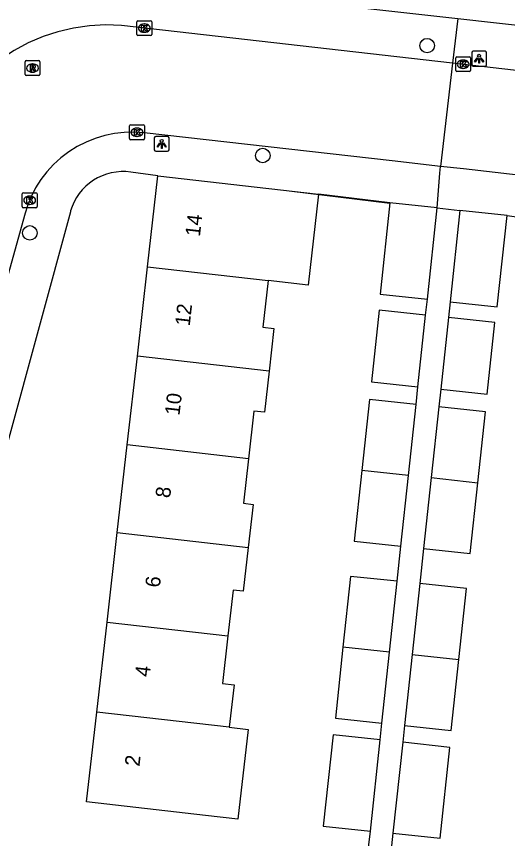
# Model space of a CAD drawing. Extents: x 162026 to 163499, y 387297 to 388169.
# Drawn here: x 162383.6 to 162416.7, y 387852 to 387907.4 of the extents above; entities that cross this region are included whole.
import ezdxf

# ---------------------------------------------------------------- set-up
doc = ezdxf.new("R2010")
doc.units = 0
for name, color, linetype in [('IMGEO_Boom', 7, 'Continuous'), ('IMGEO_Kolk', 7, 'Continuous'), ('IMGEO_Lichtpunt', 7, 'Continuous'), ('IMGEO_Muur', 7, 'Continuous'), ('IMGEO_Pand', 7, 'Continuous'), ('IMGEO_Pand_nummerreeks', 7, 'Continuous'), ('IMGEO_Rijbaan_lokaal_open', 7, 'Continuous'), ('IMGEO_Rioolput', 7, 'Continuous'), ('IMGEO_Voetpad_open', 7, 'Continuous')]:
    doc.layers.add(name, color=color, linetype=linetype)

msp = doc.modelspace()

# ---------------------------------------------------------------- linework, layer by layer
at = {"layer": 'IMGEO_Boom'}
for centre in [(162411.289, 387905.434), (162400.199, 387898.028), (162384.482, 387892.813)]:
    msp.add_circle(centre, 0.489, dxfattribs=at)
at = {"layer": 'IMGEO_Kolk'}
for p, q in [((162391.705, 387906.189), (162391.705, 387907.041)), ((162391.78, 387907.115), (162392.632, 387907.115)), ((162392.193, 387906.895), (162392.218, 387906.895)), ((162392.706, 387907.041), (162392.706, 387906.189)), ((162392.632, 387906.115), (162391.78, 387906.115)), ((162392.216, 387906.335), (162392.191, 387906.335)), ((162413.218, 387903.755), (162413.218, 387904.607)), ((162413.293, 387904.681), (162414.145, 387904.681)), ((162413.706, 387904.461), (162413.731, 387904.461)), ((162414.219, 387904.607), (162414.219, 387903.755)), ((162413.729, 387903.901), (162413.704, 387903.901)), ((162414.145, 387903.681), (162413.293, 387903.681)), ((162391.212, 387899.166), (162391.212, 387900.018)), ((162391.287, 387900.092), (162392.139, 387900.092)), ((162392.213, 387900.018), (162392.213, 387899.166)), ((162391.7, 387899.872), (162391.725, 387899.872)), ((162392.139, 387899.092), (162391.287, 387899.092)), ((162391.723, 387899.312), (162391.698, 387899.312)), ((162383.969, 387894.584), (162383.969, 387895.436)), ((162384.044, 387895.51), (162384.896, 387895.51)), ((162384.457, 387895.29), (162384.482, 387895.29)), ((162384.97, 387895.436), (162384.97, 387894.584)), ((162384.896, 387894.51), (162384.044, 387894.51)), ((162384.48, 387894.73), (162384.455, 387894.73))]:
    msp.add_line(p, q, dxfattribs=at)
for points in [[(162391.705, 387906.189), (162391.705, 387907.041)], [(162391.78, 387907.115), (162392.632, 387907.115)], [(162392.026, 387906.815), (162392.149, 387906.815), (162392.149, 387906.664), (162392.279, 387906.815), (162392.443, 387906.815), (162392.297, 387906.664), (162392.45, 387906.415), (162392.298, 387906.415), (162392.213, 387906.579), (162392.149, 387906.512), (162392.149, 387906.415), (162392.026, 387906.415), (162392.026, 387906.815)], [(162392.706, 387907.041), (162392.706, 387906.189)], [(162392.632, 387906.115), (162391.78, 387906.115)], [(162413.218, 387903.755), (162413.218, 387904.607)], [(162413.293, 387904.681), (162414.145, 387904.681)], [(162414.219, 387904.607), (162414.219, 387903.755)], [(162413.539, 387904.381), (162413.662, 387904.381), (162413.662, 387904.23), (162413.792, 387904.381), (162413.956, 387904.381), (162413.81, 387904.23), (162413.963, 387903.981), (162413.811, 387903.981), (162413.726, 387904.145), (162413.662, 387904.078), (162413.662, 387903.981), (162413.539, 387903.981), (162413.539, 387904.381)], [(162414.145, 387903.681), (162413.293, 387903.681)], [(162391.212, 387899.166), (162391.212, 387900.018)], [(162391.287, 387900.092), (162392.139, 387900.092)], [(162392.213, 387900.018), (162392.213, 387899.166)], [(162391.533, 387899.792), (162391.656, 387899.792), (162391.656, 387899.641), (162391.786, 387899.792), (162391.95, 387899.792), (162391.804, 387899.641), (162391.957, 387899.392), (162391.805, 387899.392), (162391.72, 387899.556), (162391.656, 387899.489), (162391.656, 387899.392), (162391.533, 387899.392), (162391.533, 387899.792)], [(162392.139, 387899.092), (162391.287, 387899.092)], [(162383.969, 387894.584), (162383.969, 387895.436)], [(162384.044, 387895.51), (162384.896, 387895.51)], [(162384.29, 387895.21), (162384.413, 387895.21), (162384.413, 387895.059), (162384.543, 387895.21), (162384.707, 387895.21), (162384.561, 387895.059), (162384.714, 387894.81), (162384.562, 387894.81), (162384.477, 387894.974), (162384.413, 387894.907), (162384.413, 387894.81), (162384.29, 387894.81), (162384.29, 387895.21)], [(162384.97, 387895.436), (162384.97, 387894.584)], [(162384.896, 387894.51), (162384.044, 387894.51)]]:
    msp.add_lwpolyline(points, dxfattribs=at)
for centre, start, end in [((162391.782, 387907.039), 91.552, 178.448), ((162391.782, 387907.039), 91.552, 178.448), ((162392.63, 387907.039), 1.552, 88.448), ((162392.63, 387907.039), 1.552, 88.448), ((162391.782, 387906.191), 181.552, 268.448), ((162391.782, 387906.191), 181.552, 268.448), ((162392.63, 387906.191), 271.552, 358.448), ((162392.63, 387906.191), 271.552, 358.448), ((162413.295, 387904.605), 91.552, 178.448), ((162413.295, 387904.605), 91.552, 178.448), ((162414.143, 387904.605), 1.552, 88.448), ((162414.143, 387904.605), 1.552, 88.448), ((162413.295, 387903.757), 181.552, 268.448), ((162413.295, 387903.757), 181.552, 268.448), ((162414.143, 387903.757), 271.552, 358.448), ((162414.143, 387903.757), 271.552, 358.448), ((162391.289, 387900.016), 91.552, 178.448), ((162391.289, 387900.016), 91.552, 178.448), ((162392.137, 387900.016), 1.552, 88.448), ((162392.137, 387900.016), 1.552, 88.448), ((162391.289, 387899.168), 181.552, 268.448), ((162391.289, 387899.168), 181.552, 268.448), ((162392.137, 387899.168), 271.552, 358.448), ((162392.137, 387899.168), 271.552, 358.448), ((162384.046, 387895.434), 91.552, 178.448), ((162384.046, 387895.434), 91.552, 178.448), ((162384.894, 387895.434), 1.552, 88.448), ((162384.894, 387895.434), 1.552, 88.448), ((162384.046, 387894.586), 181.552, 268.448), ((162384.046, 387894.586), 181.552, 268.448), ((162384.894, 387894.586), 271.552, 358.448), ((162384.894, 387894.586), 271.552, 358.448)]:
    msp.add_arc(centre, 0.0765, start, end, dxfattribs=at)
for centre, major_axis, ratio, start_param, end_param in [((162392.192, 387906.615), (-0.387, 0.002), 0.722429, 4.712389, 7.853982), ((162392.217, 387906.615), (-0.39, 0.002), 0.717154, 1.570796, 4.712389), ((162413.705, 387904.181), (-0.387, 0.002), 0.722429, 4.712389, 7.853982), ((162413.73, 387904.181), (-0.39, 0.002), 0.717154, 1.570796, 4.712389), ((162391.699, 387899.592), (-0.387, 0.002), 0.722429, 4.712389, 7.853982), ((162391.724, 387899.592), (-0.39, 0.002), 0.717154, 1.570796, 4.712389), ((162384.456, 387895.01), (-0.387, 0.002), 0.722429, 4.712389, 7.853982), ((162384.481, 387895.01), (-0.39, 0.002), 0.717154, 1.570796, 4.712389)]:
    msp.add_ellipse(centre, major_axis=major_axis, ratio=ratio, start_param=start_param, end_param=end_param, dxfattribs=at)
at = {"layer": 'IMGEO_Lichtpunt'}
for p, q in [((162414.299, 387904.956), (162414.299, 387904.149)), ((162414.299, 387904.956), (162414.299, 387904.149)), ((162415.201, 387905.051), (162414.393, 387905.051)), ((162415.201, 387905.051), (162414.393, 387905.051)), ((162415.295, 387904.149), (162415.295, 387904.956)), ((162415.295, 387904.149), (162415.295, 387904.956)), ((162414.393, 387904.055), (162415.201, 387904.055)), ((162414.393, 387904.055), (162415.201, 387904.055)), ((162392.879, 387899.214), (162392.879, 387898.407)), ((162392.879, 387899.214), (162392.879, 387898.407)), ((162393.781, 387899.309), (162392.973, 387899.309)), ((162393.781, 387899.309), (162392.973, 387899.309)), ((162393.875, 387898.407), (162393.875, 387899.214)), ((162393.875, 387898.407), (162393.875, 387899.214)), ((162392.973, 387898.313), (162393.781, 387898.313)), ((162392.973, 387898.313), (162393.781, 387898.313))]:
    msp.add_line(p, q, dxfattribs=at)
for points in [[(162414.673, 387904.62), (162414.712, 387904.592), (162414.524, 387904.33), (162414.486, 387904.357), (162414.673, 387904.62)], [(162414.775, 387904.572), (162414.822, 387904.572), (162414.822, 387904.25), (162414.775, 387904.25), (162414.775, 387904.572)], [(162414.885, 387904.592), (162414.923, 387904.619), (162415.11, 387904.357), (162415.071, 387904.329), (162414.885, 387904.592)], [(162393.253, 387898.878), (162393.292, 387898.85), (162393.104, 387898.588), (162393.066, 387898.615), (162393.253, 387898.878)], [(162393.465, 387898.85), (162393.503, 387898.877), (162393.69, 387898.615), (162393.651, 387898.587), (162393.465, 387898.85)], [(162393.355, 387898.83), (162393.402, 387898.83), (162393.402, 387898.508), (162393.355, 387898.508), (162393.355, 387898.83)]]:
    msp.add_lwpolyline(points, dxfattribs=at)
for centre in [(162414.798, 387904.754), (162393.378, 387899.012)]:
    msp.add_circle(centre, 0.0994, dxfattribs=at)
for centre, start, end in [((162414.393, 387904.956), 90, 180), ((162414.393, 387904.956), 90, 180), ((162415.201, 387904.956), 0, 90), ((162415.201, 387904.956), 0, 90), ((162414.393, 387904.149), 180, 270), ((162414.393, 387904.149), 180, 270), ((162415.201, 387904.149), 270, 0), ((162415.201, 387904.149), 270, 360), ((162392.973, 387899.214), 90, 180), ((162392.973, 387899.214), 90, 180), ((162393.781, 387899.214), 0, 90), ((162393.781, 387899.214), 0, 90), ((162392.973, 387898.407), 180, 270), ((162392.973, 387898.407), 180, 270), ((162393.781, 387898.407), 270, 0), ((162393.781, 387898.407), 270, 360)]:
    msp.add_arc(centre, 0.0946, start, end, dxfattribs=at)
at = {"layer": 'IMGEO_Muur'}
msp.add_lwpolyline([(162402.165, 387895.619), (162408.764, 387894.82)], dxfattribs=at)
at = {"layer": 'IMGEO_Pand'}
for points in [[(162392.425, 387890.522), (162393.125, 387896.651)], [(162393.125, 387896.651), (162403.967, 387895.413)], [(162403.967, 387895.413), (162403.267, 387889.284), (162400.563, 387889.593)], [(162408.78, 387894.837), (162408.121, 387888.692), (162411.303, 387888.351)], [(162411.961, 387894.496), (162408.78, 387894.837)], [(162411.303, 387888.351), (162411.961, 387894.496)], [(162413.502, 387894.329), (162412.838, 387888.168)], [(162412.838, 387888.168), (162416.02, 387887.825), (162416.683, 387893.987)], [(162416.683, 387893.987), (162413.502, 387894.329)], [(162391.737, 387884.5), (162392.425, 387890.522)], [(162392.425, 387890.522), (162400.563, 387889.593)], [(162400.563, 387889.593), (162400.205, 387886.46), (162400.955, 387886.374), (162400.625, 387883.485)], [(162411.186, 387887.258), (162408.044, 387887.595), (162407.528, 387882.781), (162410.67, 387882.444)], [(162410.67, 387882.444), (162411.186, 387887.258)], [(162412.724, 387887.101), (162412.204, 387882.273)], [(162412.204, 387882.273), (162415.346, 387881.935), (162415.865, 387886.763), (162412.724, 387887.101)], [(162391.054, 387878.526), (162391.737, 387884.5)], [(162400.625, 387883.485), (162391.737, 387884.5)], [(162400.625, 387883.485), (162400.309, 387880.719), (162399.6, 387880.8), (162399.234, 387877.592)], [(162410.541, 387881.241), (162407.399, 387881.578), (162406.888, 387876.805)], [(162410.03, 387876.468), (162410.541, 387881.241)], [(162412.077, 387881.095), (162411.562, 387876.312)], [(162414.704, 387875.974), (162415.219, 387880.756), (162412.077, 387881.095)], [(162390.378, 387872.606), (162391.054, 387878.526)], [(162399.234, 387877.592), (162391.054, 387878.526)], [(162399.234, 387877.592), (162398.89, 387874.586), (162399.553, 387874.51), (162399.22, 387871.596)], [(162406.888, 387876.805), (162406.377, 387872.033), (162409.519, 387871.697)], [(162410.03, 387876.468), (162406.888, 387876.805)], [(162409.519, 387871.697), (162410.03, 387876.468)], [(162411.562, 387876.312), (162411.047, 387871.534)], [(162411.562, 387876.312), (162414.704, 387875.974)], [(162411.047, 387871.534), (162414.189, 387871.196), (162414.704, 387875.974)], [(162389.69, 387866.582), (162390.378, 387872.606)], [(162390.378, 387872.606), (162399.22, 387871.596)], [(162399.22, 387871.596), (162398.883, 387868.651), (162398.195, 387868.729), (162397.843, 387865.651)], [(162409.265, 387869.324), (162406.123, 387869.66), (162405.611, 387864.888)], [(162408.753, 387864.551), (162409.265, 387869.324)], [(162410.793, 387869.173), (162410.278, 387864.391)], [(162413.42, 387864.052), (162413.935, 387868.835), (162410.793, 387869.173)], [(162388.996, 387860.507), (162389.69, 387866.582)], [(162389.69, 387866.582), (162397.843, 387865.651)], [(162397.843, 387865.651), (162397.477, 387862.443), (162398.259, 387862.354), (162398.196, 387861.796), (162397.934, 387859.486)], [(162405.611, 387864.888), (162405.099, 387860.109), (162408.241, 387859.772)], [(162408.753, 387864.551), (162405.611, 387864.888)], [(162408.241, 387859.772), (162408.753, 387864.551)], [(162410.278, 387864.391), (162409.762, 387859.598)], [(162409.762, 387859.598), (162412.904, 387859.259), (162413.42, 387864.052)], [(162410.278, 387864.391), (162413.42, 387864.052)], [(162397.934, 387859.486), (162399.222, 387859.326), (162398.519, 387853.292), (162396.339, 387853.531), (162388.304, 387854.449), (162388.996, 387860.507)], [(162397.934, 387859.486), (162388.996, 387860.507)], [(162408.12, 387858.642), (162404.938, 387858.982), (162404.278, 387852.819), (162407.46, 387852.478)], [(162407.46, 387852.478), (162408.12, 387858.642)], [(162409.641, 387858.474), (162408.981, 387852.343)], [(162408.981, 387852.343), (162412.162, 387852), (162412.823, 387858.131), (162409.641, 387858.474)]]:
    msp.add_lwpolyline(points, dxfattribs=at)
at = {"layer": 'IMGEO_Rijbaan_lokaal_open'}
for points in [[(162413.007, 387904.243), (162390.676, 387906.786), (162389.589, 387906.828), (162388.503, 387906.772), (162387.427, 387906.62), (162386.368, 387906.372), (162385.377, 387906.046), (162384.377, 387905.617), (162383.42, 387905.1), (162382.513, 387904.5), (162381.663, 387903.821), (162380.877, 387903.069), (162380.456, 387902.605), (162380.22, 387902.293), (162379.442, 387901.135), (162378.771, 387899.911), (162378.211, 387898.633), (162377.769, 387897.31), (162377.721, 387897.14), (162366.207, 387855.262)], [(162413.007, 387904.243), (162412.195, 387897.296)], [(162444.639, 387872.789), (162446.538, 387889.5), (162446.633, 387890.462), (162446.642, 387891.428), (162446.564, 387892.391), (162446.401, 387893.343), (162446.153, 387894.277), (162445.823, 387895.185), (162445.413, 387896.06), (162444.926, 387896.895), (162444.367, 387897.683), (162443.739, 387898.417), (162443.049, 387899.093), (162442.967, 387899.166), (162442.491, 387899.581), (162441.98, 387899.952), (162441.438, 387900.276), (162440.869, 387900.549), (162440.608, 387900.655), (162439.709, 387900.991), (162438.784, 387901.246), (162437.9, 387901.409), (162413.007, 387904.243)], [(162412.195, 387897.296), (162408.934, 387897.664), (162392.187, 387899.556), (162391.521, 387899.6), (162390.853, 387899.585), (162390.19, 387899.51), (162389.535, 387899.376), (162388.896, 387899.184), (162388.276, 387898.936), (162387.681, 387898.633), (162387.115, 387898.278), (162386.583, 387897.875), (162386.089, 387897.425), (162385.638, 387896.933), (162385.232, 387896.403), (162384.875, 387895.838), (162384.57, 387895.244), (162384.319, 387894.625), (162384.168, 387894.147), (162373.517, 387855.908)], [(162435.074, 387848.602), (162439.395, 387888.569), (162439.426, 387889.074), (162439.412, 387889.579), (162439.353, 387890.081), (162439.249, 387890.576), (162439.101, 387891.06), (162438.911, 387891.528), (162438.68, 387891.978), (162438.409, 387892.405), (162438.102, 387892.806), (162437.759, 387893.178), (162437.385, 387893.518), (162436.982, 387893.824), (162436.554, 387894.092), (162436.103, 387894.32), (162435.633, 387894.508), (162435.149, 387894.653), (162434.653, 387894.754), (162434.418, 387894.786), (162417.443, 387896.703), (162413.741, 387897.121), (162412.195, 387897.296)]]:
    msp.add_lwpolyline(points, dxfattribs=at)
at = {"layer": 'IMGEO_Rioolput'}
for p, q in [((162384.237, 387904.425), (162385.089, 387904.425)), ((162384.162, 387903.499), (162384.162, 387904.351)), ((162384.65, 387904.205), (162384.675, 387904.205)), ((162385.163, 387904.351), (162385.163, 387903.499)), ((162385.089, 387903.425), (162384.237, 387903.425)), ((162384.673, 387903.645), (162384.648, 387903.645))]:
    msp.add_line(p, q, dxfattribs=at)
for points in [[(162384.237, 387904.425), (162385.089, 387904.425)], [(162384.162, 387903.499), (162384.162, 387904.351)], [(162384.751, 387904.123), (162384.499, 387904.125), (162384.499, 387903.725)], [(162384.499, 387903.725), (162384.623, 387903.725), (162384.623, 387903.887), (162384.634, 387903.887)], [(162384.677, 387904.044), (162384.623, 387904.044), (162384.623, 387903.963)], [(162384.623, 387903.963), (162384.675, 387903.963)], [(162384.681, 387903.858), (162384.752, 387903.725), (162384.892, 387903.725), (162384.827, 387903.851)], [(162385.163, 387904.351), (162385.163, 387903.499)], [(162385.089, 387903.425), (162384.237, 387903.425)]]:
    msp.add_lwpolyline(points, dxfattribs=at)
for centre, radius, start, end in [((162384.239, 387904.349), 0.0765, 91.552, 178.448), ((162384.239, 387904.349), 0.0765, 91.552, 178.448), ((162385.087, 387904.349), 0.0765, 1.552, 88.448), ((162385.087, 387904.349), 0.0765, 1.552, 88.448), ((162384.633, 387903.834), 0.0533, 26.0293, 88.6989), ((162384.659, 387904.152), 0.19, 274.7715, 282.9687), ((162384.683, 387903.948), 0.0964, 77.0061, 93.1865), ((162384.697, 387904.005), 0.0378, 276.6634, 79.6772), ((162384.75, 387904.013), 0.109, 350.3612, 89.416), ((162384.748, 387904.013), 0.112, 277.5842, 350.9817), ((162384.732, 387903.798), 0.108, 29.5134, 73.7905), ((162384.239, 387903.501), 0.0765, 181.552, 268.448), ((162384.239, 387903.501), 0.0765, 181.552, 268.448), ((162385.087, 387903.501), 0.0765, 271.552, 358.448), ((162385.087, 387903.501), 0.0765, 271.552, 358.448)]:
    msp.add_arc(centre, radius, start, end, dxfattribs=at)
for centre, major_axis, ratio, start_param, end_param in [((162384.649, 387903.925), (-0.387, 0.002), 0.722429, 4.712389, 7.853982), ((162384.674, 387903.925), (-0.39, 0.002), 0.717154, 1.570796, 4.712389)]:
    msp.add_ellipse(centre, major_axis=major_axis, ratio=ratio, start_param=start_param, end_param=end_param, dxfattribs=at)
at = {"layer": 'IMGEO_Voetpad_open'}
for points in [[(162378.114, 387911.206), (162413.36, 387907.265)], [(162413.36, 387907.265), (162413.007, 387904.243)], [(162413.36, 387907.265), (162447.886, 387903.405)], [(162411.961, 387894.496), (162412.15, 387896.827), (162412.195, 387897.296)], [(162393.125, 387896.651), (162391.291, 387896.908), (162390.963, 387896.94), (162390.634, 387896.943), (162390.306, 387896.916), (162389.981, 387896.86), (162389.663, 387896.775), (162389.354, 387896.663), (162389.056, 387896.523), (162388.772, 387896.357), (162388.503, 387896.166), (162388.253, 387895.952), (162388.023, 387895.716), (162387.815, 387895.461), (162387.63, 387895.189), (162387.471, 387894.901), (162387.337, 387894.599), (162387.232, 387894.288), (162387.217, 387894.235), (162376.626, 387855.48)], [(162408.78, 387894.837), (162403.967, 387895.413)], [(162411.961, 387894.496), (162413.502, 387894.329)], [(162416.683, 387893.987), (162423.601, 387893.025)], [(162411.186, 387887.258), (162411.303, 387888.351)], [(162412.838, 387888.168), (162412.724, 387887.101)], [(162410.541, 387881.241), (162410.67, 387882.444)], [(162412.204, 387882.273), (162412.077, 387881.095)], [(162409.265, 387869.324), (162409.519, 387871.697)], [(162411.047, 387871.534), (162410.793, 387869.173)], [(162408.12, 387858.642), (162408.241, 387859.772)], [(162409.762, 387859.598), (162409.641, 387858.474)], [(162406.969, 387848.484), (162407.46, 387852.478)], [(162408.981, 387852.343), (162408.547, 387848.311)]]:
    msp.add_lwpolyline(points, dxfattribs=at)

# ---------------------------------------------------------------- texts
at = {"layer": 'IMGEO_Pand_nummerreeks'}
for s, rotation, p in [('14', 83.4857, (162395.956, 387892.533)), ('12', 83.483, (162395.267, 387886.502)), ('10', 83.483, (162394.579, 387880.479)), ('8', 83.483, (162393.943, 387874.908)), ('6', 83.483, (162393.253, 387868.875)), ('4', 83.483, (162392.564, 387862.846)), ('2', 83.483, (162391.876, 387856.815))]:
    msp.add_text(s, height=1, rotation=rotation, dxfattribs=at).set_placement(p)

doc.saveas('drawing.dxf')
